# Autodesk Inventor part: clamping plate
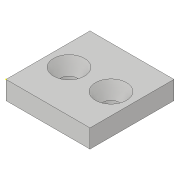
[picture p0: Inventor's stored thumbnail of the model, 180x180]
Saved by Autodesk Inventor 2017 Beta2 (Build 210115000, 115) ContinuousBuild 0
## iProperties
Created: 2016-03
Part Number: clamping plate
Material: Generic
Document SubType Name: Modeling
Designer: Sandeep
Density: 1 g/cm^3
Appearance: Default
Author: Sandeep
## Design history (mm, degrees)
sketch "Sketch1"
  geometry: L1 (0, 0)-(32, 0); L2 (32, 0)-(32, 32); L3 (32, 32)-(0, 32); L4 (0, 32)-(0, 0)
  constraints: 8 end point, 2 parallel, 1 horizontal, 1 perpendicular
  dimensions: "d0" = 32 distance between parallel lines of L1 L3; "d1" = 32 distance of L2.end L3.end
extrude "Extrusion1" new body sketch "Sketch1" distance "d2" = 7; taper "d3" = 0 deg
sketch "Sketch2"
  geometry: 1 further point
sketch "Sketch3"
  geometry: 1 further point
hole "Hole2" diameter "d15" = 6; stored, may be unused: countersink angle "d19" = 60 deg, drill point angle "d21" = 118 deg; dims "d13" = 8, "d14" = 16, "d16" = 6, "d17" = 11.78, "d18" = 2, "d20" = 8
sketch "Sketch4"
  geometry: 1 further point
hole "Hole3" diameter "d24" = 6; stored, may be unused: countersink angle "d28" = 60 deg, drill point angle "d30" = 118 deg; dims "d22" = 8, "d23" = 16, "d25" = 6, "d26" = 11.78, "d27" = 2, "d29" = 8
body "Solid1"
